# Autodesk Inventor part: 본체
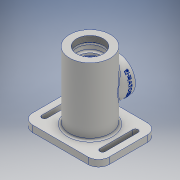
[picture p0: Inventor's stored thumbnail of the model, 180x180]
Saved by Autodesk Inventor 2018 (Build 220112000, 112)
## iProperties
Created: 2021-07
Part Number: 본체
Material: 알루미늄 6061
Document SubType Name: Modeling
Designer: 1class13
Density: 2.7 g/cm^3
Appearance: 알루미늄 - 평지
Mass: 738.025 g
Surface Area: 645.265 cm^2
Volume: 273.343 cm^3
Author: 1class13
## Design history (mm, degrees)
sketch "스케치1"
  geometry: C1 r 31 at (0, 0); 1 further point
  constraints: 1 centre point, 1 coincident
  dimensions: "d0" = 62 diameter of C1
extrude "돌출1" new body sketch "스케치1" stored distance "d1" = 115; taper "d2" = 0 deg
sketch "스케치2"
  geometry: C1 r 35 at (0, 0); 1 further point
  constraints: 1 centre point, 1 coincident
  dimensions: "d3" = 70 diameter of C1
extrude "돌출2" join sketch "스케치2" distance "d4" = 3; taper "d5" = 0 deg
node "작업 평면1"
sketch "스케치3"
  geometry: L1 (-58, 45)-(58, 45); L2 (58, 45)-(58, -45); L3 (58, -45)-(-58, -45); L4 (-58, -45)-(-58, 45); 3 further points
  constraints: 8 end point, 2 midpoint, 2 parallel, 1 horizontal, 1 horizontal alignment, 1 perpendicular, 1 vertical alignment
  dimensions: "d7" = 116 distance of L1.start L1.end; "d8" = 90 distance between parallel lines of L3 L1
extrude "돌출3" join sketch "스케치3" stored distance "d9" = 10; taper "d10" = 0 deg
fillet "모깎기1" dims "d11" = 16
sketch "스케치4"
  geometry: L1 (-44, 25)-(-44, -25); L2 (-40, 25)-(-40, -25); L3 (-48, -25)-(-48, 25); A1 r 4 centre (-44, 25) between (-40, 25) and (-48, 25); A2 r 4 centre (-44, -25) between (-48, -25) and (-40, -25); 2 further points
  constraints: 8 end point, 4 point on circle, 4 tangent, 2 centre point, 1 horizontal alignment, 1 midpoint, 1 parallel, 1 vertical
  dimensions: "d12" = 4 radius of A1; "d13" = 50 distance of L1.end L1.start; "d14" = 44 distance of point (0, 0) point (-44, 0)
extrude "돌출4" cut sketch "스케치4" extent not by distance; stored distance "d15" = 10; taper "d16" = 0 deg
node "작업 평면2"
sketch "스케치5"
  geometry: L1 (31, 57.5)-(-31, 57.5) reference; C1 r 27 at (0, 1.5); 1 further point
  constraints: 1 centre point, 1 vertical alignment
  dimensions: "d18" = 54 diameter of C1; "d19" = 56 distance from line of L1 C1.centre
extrude "돌출5" join sketch "스케치5" stored distance "d20" = 50; taper "d21" = 0 deg
hole "구멍1" diameter "d24" = 40.376; stored, may be unused: countersink angle "d28" = 90 deg, drill point angle "d30" = 0 deg; dims "d25" = 84, "d26" = 4, "d27" = 2, "d29" = 9, "d31" = 10, "d32" = 10
sketch "스케치7"
  geometry: L1 (0, 57.099)-(0, -57.5); L2 (35, -57.5)-(-35, -57.5) reference; L3 (20.188, 48.5)-(-20.188, 48.5) reference; L4 (0, 48.5)-(24, 48.5); L5 (24, 48.5)-(24, 45.5); L6 (24, 45.5)-(0, 45.5); L7 (0, 45.5)-(0, 48.5); L8 (0, 45.5)-(20, 45.5); L9 (20, 45.5)-(20, 36.5); L10 (20, 36.5)-(0, 36.5); L11 (0, 36.5)-(0, 45.5); L12 (0, 36.5)-(17.5, 36.5); L13 (17.5, 36.5)-(17.5, 33.25); L14 (17.5, 33.25)-(0, 33.25); L15 (0, 33.25)-(0, 36.5); L16 (0, 33.25)-(18.5, 33.25); L17 (18.5, 33.25)-(18.5, 31.5); L18 (18.5, 31.5)-(0, 31.5); L19 (0, 31.5)-(0, 33.25); L20 (0, 31.5)-(17.5, 31.5); L21 (17.5, 31.5)-(17.5, 20.5); L22 (17.5, 20.5)-(0, 20.5); L23 (0, 20.5)-(0, 31.5); L24 (0, 20.5)-(26, 20.5); L25 (26, 20.5)-(26, -17.5); L26 (26, -17.5)-(0, -17.5); L27 (0, -17.5)-(0, 20.5); L28 (0, -17.5)-(17.5, -17.5); L29 (17.5, -17.5)-(17.5, -28.5); L30 (17.5, -28.5)-(0, -28.5); L31 (0, -28.5)-(0, -17.5); L32 (0, -28.5)-(16, -28.5); L33 (16, -28.5)-(16, -33.5); L34 (16, -33.5)-(0, -33.5); L35 (0, -33.5)-(0, -28.5); L36 (0, -33.5)-(10, -33.5); L37 (10, -33.5)-(10, -36.2); L38 (10, -36.2)-(0, -36.2); L39 (0, -36.2)-(0, -33.5); L40 (0, -36.2)-(12.5, -36.2); L41 (12.5, -36.2)-(12.5, -43.5); L42 (12.5, -43.5)-(0, -43.5); L43 (0, -43.5)-(0, -36.2); L44 (0, -43.5)-(16, -43.5); L45 (16, -43.5)-(16, -57.5); L46 (16, -57.5)-(0, -57.5); L47 (0, -57.5)-(0, -43.5); L48 (16, -43.5)-(22, -57.5); L49 (-20.188, 57.5)-(20.188, 57.5) reference; 1 further point
  constraints: 92 end point, 22 parallel, 11 horizontal, 11 perpendicular, 4 point on line, 2 midpoint
  dimensions: "d33" = 48 diameter of L5 L1; "d34" = 40 diameter of L9 L11; "d35" = 35 diameter of L13 L15; "d36" = 37 diameter of L17 L19; "d37" = 52 diameter of L25 L1; "d38" = 32 diameter of L33 L1; "d39" = 20 diameter of L37 L1; "d40" = 25 diameter of L41 L1; "d41" = 44 diameter of L48.end L1; "d42" = 32 diameter of L45 L1; "d43" = 14 distance between parallel lines of L2 L44; "d44" = 7.3 distance between parallel lines of L42 L38; "d45" = 24 distance between parallel lines of L2 L34; "d46" = 12 distance between parallel lines of L49 L8; "d47" = 21 distance between parallel lines of L49 L12; "d48" = 1.75 distance between parallel lines of L18 L14; "d49" = 11 distance between parallel lines of L22 L18; "d50" = 11 distance between parallel lines of L30 L26; "d51" = 38 distance between parallel lines of L22 L26; "d52" = 65 distance between parallel lines of L30 L12
revolve "회전1" sketch "스케치7" stored, may be unused: angle "d53" = 90 deg
hole "구멍2" diameter "d56" = 32; stored, may be unused: countersink angle "d60" = 90 deg, drill point angle "d62" = 118 deg; dims "d54" = 10, "d55" = 10, "d57" = 84, "d58" = 4, "d59" = 2, "d61" = 9
sketch "스케치8" dims "d63" = 44
  geometry: 3 further points
  constraints: 2 horizontal alignment, 1 vertical alignment, 2 other
  dimensions: "d64" = 1.5 distance of point (0, 1.5) point (0, 0)
hole "구멍3" sketch "스케치8" at (22, 0) diameter "d65" = 2.459; stored, may be unused: countersink angle "d69" = 90 deg, drill point angle "d71" = 118 deg; dims "d66" = 6, "d67" = 4, "d68" = 2, "d70" = 8
fillet "모깎기2" dims "d72" = 3
fillet "모깎기3" dims "d73" = 3
fillet "모깎기4" dims "d74" = 3
fillet "모깎기5" dims "d75" = 3
fillet "모깎기6" dims "d76" = 0.3
chamfer "모따기1" distance "d77" = 0.7; stored, may be unused: second distance "d78" = 2, angle "d79" = 30 deg
chamfer "모따기2" distance "d80" = 1; stored, may be unused: second distance "d81" = 2, angle "d82" = 30 deg
chamfer "모따기3" distance "d83" = 1; stored, may be unused: second distance "d84" = 2, angle "d85" = 30 deg
chamfer "모따기4" distance "d86" = 1; stored, may be unused: second distance "d87" = 2, angle "d88" = 30 deg
fillet "모깎기7" dims "d89" = 3
fillet "모깎기8" dims "d91" = 3
node "작업 평면3"
sketch "스케치11"
  geometry: L1 (0, 27)-(0, -27) reference; 3 further points
  constraints: 1 horizontal alignment, 1 midpoint, 1 other
  dimensions: "d92" = 8 distance from line of L1 point (-8, 0)
feature "엠보싱1" sketch "스케치11" dims "d93" = 0.5, "d94" = 0
node "솔리드1"
mirror "미러1"
mirror "미러2"
other parameters: "d6" = -44.5, "d17" = 42
